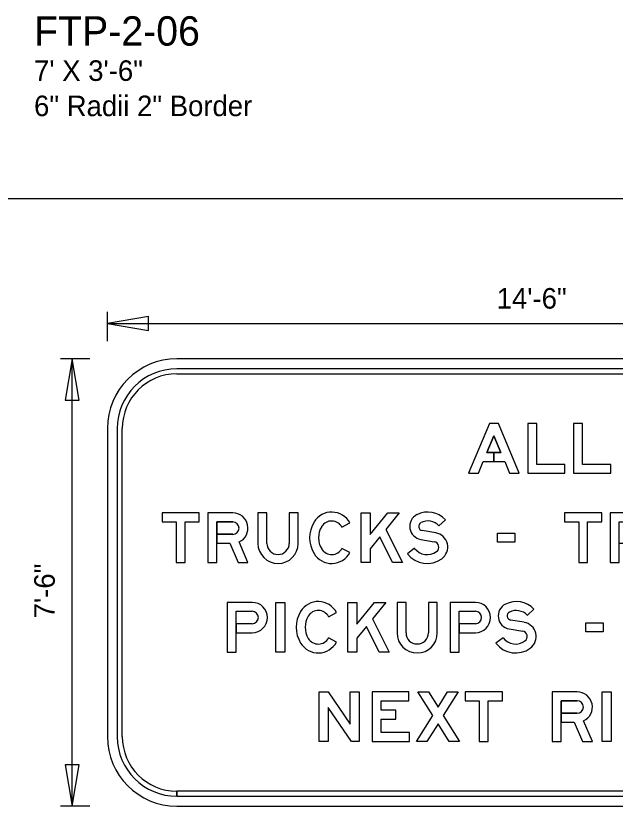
# Model space of a CAD drawing. Extents: x 0 to 770, y 0 to 495.
# Drawn here: x 195.9 to 297.9, y 226.6 to 361.1 of the extents above; entities that cross this region are included whole.
import ezdxf

# ---------------------------------------------------------------- set-up
doc = ezdxf.new("R2010")
doc.units = 0
for name, color, linetype in [('Dimension', 7, 'Continuous'), ('GSBWFill', 7, 'Continuous'), ('GSColorFill', 7, 'Continuous'), ('GSDims', 7, 'Continuous'), ('GSOutline', 7, 'Continuous'), ('SheetLines_dp', 7, 'Continuous'), ('TextStructures', 7, 'Continuous')]:
    doc.layers.add(name, color=color, linetype=linetype)

msp = doc.modelspace()

# ---------------------------------------------------------------- linework, layer by layer
at = {"layer": 'Dimension'}
for points in [[(211.47, 308.76), (218.49, 307.57), (218.49, 309.95)], [(205.48, 302.76), (204.29, 295.75), (206.67, 295.75)], [(205.48, 226.64), (206.67, 233.66), (204.29, 233.66)]]:
    msp.add_lwpolyline(points, close=True, dxfattribs=at)
at = {"layer": 'GSBWFill'}
for p, q in [((346.81, 302.76), (223.31, 302.76)), ((346.81, 301.07), (223.31, 301.07)), ((223.31, 300.23), (346.81, 300.23)), ((211.47, 290.92), (211.47, 238.48)), ((213.16, 290.92), (213.16, 238.48)), ((214.01, 238.48), (214.01, 290.92)), ((242.43, 276.54), (242.43, 271.36)), ((251.41, 274.12), (252.75, 274.83)), ((267.92, 274.34), (269.03, 275.38)), ((267.37, 273.15), (265.06, 273.54)), ((264.81, 272.04), (267.11, 271.65)), ((252.75, 269.8), (251.41, 270.51)), ((251.41, 270.51), (251.41, 270.51)), ((263.77, 270.52), (262.56, 269.59)), ((266.11, 261.32), (266.11, 256.14)), ((233.38, 259.8), (236.13, 259.8)), ((249.12, 258.89), (250.47, 259.61)), ((271.36, 259.8), (274.11, 259.8)), ((282.97, 259.12), (284.09, 260.16)), ((282.42, 257.93), (280.12, 258.31)), ((279.87, 256.81), (282.17, 256.42)), ((250.47, 254.57), (249.12, 255.29)), ((249.12, 255.29), (249.12, 255.29)), ((278.82, 255.29), (277.62, 254.36)), ((223.31, 228.33), (223.31, 229.18)), ((346.81, 229.18), (223.32, 229.18)), ((223.32, 229.18), (223.32, 228.33)), ((223.32, 228.33), (346.81, 228.33)), ((223.31, 226.64), (346.81, 226.64))]:
    msp.add_line(p, q, dxfattribs=at)
for points in [[(278.47, 286.82), (277.28, 286.82), (277.28, 285.3), (279.11, 285.3), (279.94, 283.31), (281.59, 283.31), (278.04, 291.77), (276.52, 291.77), (272.96, 283.31), (274.62, 283.31), (275.45, 285.3), (277.28, 285.3), (277.28, 286.82), (276.09, 286.82), (277.28, 289.65)], [(289.37, 283.31), (289.37, 284.79), (284.55, 284.79), (284.55, 291.77), (283.03, 291.77), (283.03, 283.31)], [(297.16, 283.31), (297.16, 284.79), (292.33, 284.79), (292.33, 291.77), (290.81, 291.77), (290.81, 283.31)], [(220.78, 275.02), (223.19, 275.02), (223.19, 268.09), (224.71, 268.09), (224.71, 275.02), (227.12, 275.02), (227.12, 276.54), (220.78, 276.54)], [(261.17, 276.54), (258.9, 273.75), (261.71, 268.09), (260.01, 268.09), (257.84, 272.45), (256.22, 270.45), (256.22, 268.09), (254.69, 268.09), (254.69, 276.54), (256.22, 276.54), (256.22, 272.87), (259.2, 276.54)], [(289.29, 275.02), (291.7, 275.02), (291.7, 268.09), (293.22, 268.09), (293.22, 275.02), (295.63, 275.02), (295.63, 276.54), (289.29, 276.54)], [(277.87, 273.08), (280.83, 273.08), (280.83, 271.55), (277.87, 271.55)], [(240.15, 252.86), (240.15, 261.32), (241.67, 261.32), (241.67, 252.86)], [(258.88, 261.32), (256.61, 258.53), (259.43, 252.86), (257.73, 252.86), (255.56, 257.23), (253.93, 255.23), (253.93, 252.86), (252.41, 252.86), (252.41, 261.32), (253.93, 261.32), (253.93, 257.64), (256.92, 261.32)], [(292.93, 257.85), (295.89, 257.85), (295.89, 256.33), (292.93, 256.33)], [(254.36, 246.09), (254.36, 237.64), (253.05, 237.64), (249.03, 243.43), (249.03, 237.64), (247.5, 237.64), (247.5, 246.09), (249.03, 246.09), (252.83, 240.61), (252.83, 246.09)], [(262.9, 239.16), (258.08, 239.16), (258.08, 241.43), (260.57, 241.43), (260.57, 242.96), (258.08, 242.96), (258.08, 244.57), (262.77, 244.57), (262.77, 246.09), (256.56, 246.09), (256.56, 237.64), (262.9, 237.64)], [(269.64, 237.64), (267.76, 240.63), (265.88, 237.64), (264.08, 237.64), (266.86, 242.07), (264.34, 246.09), (266.13, 246.09), (267.76, 243.5), (269.39, 246.09), (271.19, 246.09), (268.66, 242.07), (271.44, 237.64)], [(272.37, 244.57), (274.78, 244.57), (274.78, 237.64), (276.31, 237.64), (276.31, 244.57), (278.72, 244.57), (278.72, 246.09), (272.37, 246.09)], [(295.72, 237.64), (295.72, 246.09), (297.24, 246.09), (297.24, 237.64)]]:
    msp.add_lwpolyline(points, close=True, dxfattribs=at)
for points in [[(232.83, 276.54), (228.56, 276.54), (228.56, 268.09), (230.08, 268.09), (230.08, 275.02), (232.83, 275.02)], [(238.62, 271.36), (238.62, 276.54), (237.1, 276.54), (237.1, 271.36)], [(243.95, 271.36), (243.95, 276.54), (242.43, 276.54)], [(301.34, 276.54), (297.07, 276.54), (297.07, 268.09), (298.59, 268.09), (298.59, 275.02), (301.34, 275.02)], [(232.83, 272.91), (230.08, 272.91), (230.08, 271.38)], [(230.08, 271.38), (232.32, 271.38), (233.75, 268.09), (235.41, 268.09), (233.88, 271.61)], [(236.13, 261.32), (231.86, 261.32), (231.86, 252.86), (233.38, 252.86), (233.38, 259.8)], [(262.31, 256.14), (262.31, 261.32), (260.78, 261.32), (260.78, 256.14)], [(267.64, 256.14), (267.64, 261.32), (266.11, 261.32)], [(274.11, 261.32), (269.83, 261.32), (269.83, 252.86), (271.36, 252.86), (271.36, 259.8)], [(236.13, 257.68), (233.38, 257.68), (233.38, 256.16), (236.13, 256.16)], [(274.11, 257.68), (271.36, 257.68), (271.36, 256.16), (274.11, 256.16)], [(291.45, 246.09), (287.17, 246.09), (287.17, 237.64), (288.7, 237.64), (288.7, 244.57), (291.45, 244.57)], [(291.45, 242.46), (288.7, 242.46), (288.7, 240.93)], [(288.7, 240.93), (290.94, 240.93), (292.37, 237.64), (294.03, 237.64), (292.5, 241.16)]]:
    msp.add_lwpolyline(points, dxfattribs=at)
for centre, radius, start, end in [((223.31, 290.92), 11.84, 90, 180), ((223.31, 290.92), 10.15, 90, 180), ((223.31, 290.92), 9.3, 90, 180), ((265.18, 274.25), 2.24, 116.9123, 260.4087), ((266.03, 272.59), 4.1, 42.8759, 116.9123), ((265.18, 274.25), 0.719, 116.9123, 260.4087), ((266.03, 272.59), 2.58, 42.8759, 116.9123), ((266.96, 270.73), 2.45, 306.123, 80.4087), ((240.53, 271.36), 3.43, 180, 0), ((240.53, 271.36), 1.9, 180, 0), ((265.91, 272.17), 2.71, 217.5895, 306.123), ((266.96, 270.73), 0.93, 306.123, 80.4087), ((265.91, 272.17), 4.23, 217.5895, 306.123), ((236.13, 258.74), 2.58, 270, 90), ((280.24, 259.02), 2.24, 116.9123, 260.4087), ((281.08, 257.36), 4.1, 42.8759, 116.9123), ((236.13, 258.74), 1.06, 270, 90), ((280.24, 259.02), 0.719, 116.9123, 260.4087), ((281.08, 257.36), 2.58, 42.8759, 116.9123), ((282.01, 255.51), 2.45, 306.123, 80.4087), ((264.21, 256.14), 3.43, 180, 0), ((264.21, 256.14), 1.9, 180, 0), ((282.01, 255.51), 0.93, 306.123, 80.4087), ((280.97, 256.94), 4.23, 217.5895, 306.123), ((280.97, 256.94), 2.71, 217.5895, 306.123), ((223.31, 238.48), 11.84, 180, 270), ((223.31, 238.48), 10.15, 180, 270), ((223.31, 238.48), 9.3, 180, 270)]:
    msp.add_arc(centre, radius, start, end, dxfattribs=at)
for centre, major_axis, start_param, end_param in [((232.83, 273.96), (0, 2.58), 3.562504, 6.283185), ((249.65, 273.18), (0, 3.51), 5.201543, 7.308565), ((232.83, 273.96), (0, 1.06), 3.141593, 6.283185), ((251.08, 272.31), (0, 5.18), 1.025379, 2.116213), ((249.65, 273.18), (0, 1.99), 5.201543, 7.308565), ((251.08, 272.31), (0, 3.66), 1.025379, 2.116213), ((249.65, 271.45), (0, 1.99), 2.116213, 4.223235), ((249.65, 271.45), (0, 3.51), 2.116213, 4.223235), ((247.37, 257.96), (0, 3.51), 5.201543, 7.308565), ((274.11, 258.74), (0, 2.58), 3.141593, 6.283185), ((248.8, 257.09), (0, 5.18), 1.025379, 2.116213), ((247.37, 257.96), (0, 1.99), 5.201543, 7.308565), ((274.11, 258.74), (0, 1.06), 3.141593, 6.283185), ((248.8, 257.09), (0, 3.66), 1.025379, 2.116213), ((247.37, 256.22), (0, 3.51), 2.116213, 4.223235), ((247.37, 256.22), (0, 1.99), 2.116213, 4.223235), ((291.45, 243.51), (0, 2.58), 3.562504, 6.283185), ((291.45, 243.51), (0, 1.06), 3.141593, 6.283185)]:
    msp.add_ellipse(centre, major_axis=major_axis, ratio=0.999994, start_param=start_param, end_param=end_param, dxfattribs=at)
at = {"layer": 'GSColorFill'}
for p, q in [((242.43, 276.54), (242.43, 271.36)), ((251.41, 274.12), (252.75, 274.83)), ((267.92, 274.34), (269.03, 275.38)), ((267.37, 273.15), (265.06, 273.54)), ((264.81, 272.04), (267.11, 271.65)), ((252.75, 269.8), (251.41, 270.51)), ((251.41, 270.51), (251.41, 270.51)), ((263.77, 270.52), (262.56, 269.59)), ((266.11, 261.32), (266.11, 256.14)), ((233.38, 259.8), (236.13, 259.8)), ((249.12, 258.89), (250.47, 259.61)), ((271.36, 259.8), (274.11, 259.8)), ((282.97, 259.12), (284.09, 260.16)), ((282.42, 257.93), (280.12, 258.31)), ((279.87, 256.81), (282.17, 256.42)), ((250.47, 254.57), (249.12, 255.29)), ((249.12, 255.29), (249.12, 255.29)), ((278.82, 255.29), (277.62, 254.36))]:
    msp.add_line(p, q, dxfattribs=at)
for points in [[(278.47, 286.82), (277.28, 286.82), (277.28, 285.3), (279.11, 285.3), (279.94, 283.31), (281.59, 283.31), (278.04, 291.77), (276.52, 291.77), (272.96, 283.31), (274.62, 283.31), (275.45, 285.3), (277.28, 285.3), (277.28, 286.82), (276.09, 286.82), (277.28, 289.65)], [(289.37, 283.31), (289.37, 284.79), (284.55, 284.79), (284.55, 291.77), (283.03, 291.77), (283.03, 283.31)], [(297.16, 283.31), (297.16, 284.79), (292.33, 284.79), (292.33, 291.77), (290.81, 291.77), (290.81, 283.31)], [(220.78, 275.02), (223.19, 275.02), (223.19, 268.09), (224.71, 268.09), (224.71, 275.02), (227.12, 275.02), (227.12, 276.54), (220.78, 276.54)], [(261.17, 276.54), (258.9, 273.75), (261.71, 268.09), (260.01, 268.09), (257.84, 272.45), (256.22, 270.45), (256.22, 268.09), (254.69, 268.09), (254.69, 276.54), (256.22, 276.54), (256.22, 272.87), (259.2, 276.54)], [(289.29, 275.02), (291.7, 275.02), (291.7, 268.09), (293.22, 268.09), (293.22, 275.02), (295.63, 275.02), (295.63, 276.54), (289.29, 276.54)], [(277.87, 273.08), (280.83, 273.08), (280.83, 271.55), (277.87, 271.55)], [(240.15, 252.86), (240.15, 261.32), (241.67, 261.32), (241.67, 252.86)], [(258.88, 261.32), (256.61, 258.53), (259.43, 252.86), (257.73, 252.86), (255.56, 257.23), (253.93, 255.23), (253.93, 252.86), (252.41, 252.86), (252.41, 261.32), (253.93, 261.32), (253.93, 257.64), (256.92, 261.32)], [(292.93, 257.85), (295.89, 257.85), (295.89, 256.33), (292.93, 256.33)], [(254.36, 246.09), (254.36, 237.64), (253.05, 237.64), (249.03, 243.43), (249.03, 237.64), (247.5, 237.64), (247.5, 246.09), (249.03, 246.09), (252.83, 240.61), (252.83, 246.09)], [(262.9, 239.16), (258.08, 239.16), (258.08, 241.43), (260.57, 241.43), (260.57, 242.96), (258.08, 242.96), (258.08, 244.57), (262.77, 244.57), (262.77, 246.09), (256.56, 246.09), (256.56, 237.64), (262.9, 237.64)], [(269.64, 237.64), (267.76, 240.63), (265.88, 237.64), (264.08, 237.64), (266.86, 242.07), (264.34, 246.09), (266.13, 246.09), (267.76, 243.5), (269.39, 246.09), (271.19, 246.09), (268.66, 242.07), (271.44, 237.64)], [(272.37, 244.57), (274.78, 244.57), (274.78, 237.64), (276.31, 237.64), (276.31, 244.57), (278.72, 244.57), (278.72, 246.09), (272.37, 246.09)], [(295.72, 237.64), (295.72, 246.09), (297.24, 246.09), (297.24, 237.64)]]:
    msp.add_lwpolyline(points, close=True, dxfattribs=at)
for points in [[(232.83, 276.54), (228.56, 276.54), (228.56, 268.09), (230.08, 268.09), (230.08, 275.02), (232.83, 275.02)], [(238.62, 271.36), (238.62, 276.54), (237.1, 276.54), (237.1, 271.36)], [(243.95, 271.36), (243.95, 276.54), (242.43, 276.54)], [(301.34, 276.54), (297.07, 276.54), (297.07, 268.09), (298.59, 268.09), (298.59, 275.02), (301.34, 275.02)], [(232.83, 272.91), (230.08, 272.91), (230.08, 271.38)], [(230.08, 271.38), (232.32, 271.38), (233.75, 268.09), (235.41, 268.09), (233.88, 271.61)], [(236.13, 261.32), (231.86, 261.32), (231.86, 252.86), (233.38, 252.86), (233.38, 259.8)], [(262.31, 256.14), (262.31, 261.32), (260.78, 261.32), (260.78, 256.14)], [(267.64, 256.14), (267.64, 261.32), (266.11, 261.32)], [(274.11, 261.32), (269.83, 261.32), (269.83, 252.86), (271.36, 252.86), (271.36, 259.8)], [(236.13, 257.68), (233.38, 257.68), (233.38, 256.16), (236.13, 256.16)], [(274.11, 257.68), (271.36, 257.68), (271.36, 256.16), (274.11, 256.16)], [(291.45, 246.09), (287.17, 246.09), (287.17, 237.64), (288.7, 237.64), (288.7, 244.57), (291.45, 244.57)], [(291.45, 242.46), (288.7, 242.46), (288.7, 240.93)], [(288.7, 240.93), (290.94, 240.93), (292.37, 237.64), (294.03, 237.64), (292.5, 241.16)]]:
    msp.add_lwpolyline(points, dxfattribs=at)
for centre, radius, start, end in [((265.18, 274.25), 2.24, 116.9123, 260.4087), ((266.03, 272.59), 4.1, 42.8759, 116.9123), ((265.18, 274.25), 0.719, 116.9123, 260.4087), ((266.03, 272.59), 2.58, 42.8759, 116.9123), ((266.96, 270.73), 2.45, 306.123, 80.4087), ((240.53, 271.36), 3.43, 180, 0), ((240.53, 271.36), 1.9, 180, 0), ((265.91, 272.17), 2.71, 217.5895, 306.123), ((266.96, 270.73), 0.93, 306.123, 80.4087), ((265.91, 272.17), 4.23, 217.5895, 306.123), ((236.13, 258.74), 2.58, 270, 90), ((280.24, 259.02), 2.24, 116.9123, 260.4087), ((281.08, 257.36), 4.1, 42.8759, 116.9123), ((236.13, 258.74), 1.06, 270, 90), ((280.24, 259.02), 0.719, 116.9123, 260.4087), ((281.08, 257.36), 2.58, 42.8759, 116.9123), ((282.01, 255.51), 2.45, 306.123, 80.4087), ((264.21, 256.14), 3.43, 180, 0), ((264.21, 256.14), 1.9, 180, 0), ((282.01, 255.51), 0.93, 306.123, 80.4087), ((280.97, 256.94), 4.23, 217.5895, 306.123), ((280.97, 256.94), 2.71, 217.5895, 306.123)]:
    msp.add_arc(centre, radius, start, end, dxfattribs=at)
for centre, major_axis, start_param, end_param in [((232.83, 273.96), (0, 2.58), 3.562504, 6.283185), ((249.65, 273.18), (0, 3.51), 5.201543, 7.308565), ((232.83, 273.96), (0, 1.06), 3.141593, 6.283185), ((251.08, 272.31), (0, 5.18), 1.025379, 2.116213), ((249.65, 273.18), (0, 1.99), 5.201543, 7.308565), ((251.08, 272.31), (0, 3.66), 1.025379, 2.116213), ((249.65, 271.45), (0, 1.99), 2.116213, 4.223235), ((249.65, 271.45), (0, 3.51), 2.116213, 4.223235), ((247.37, 257.96), (0, 3.51), 5.201543, 7.308565), ((274.11, 258.74), (0, 2.58), 3.141593, 6.283185), ((248.8, 257.09), (0, 5.18), 1.025379, 2.116213), ((247.37, 257.96), (0, 1.99), 5.201543, 7.308565), ((274.11, 258.74), (0, 1.06), 3.141593, 6.283185), ((248.8, 257.09), (0, 3.66), 1.025379, 2.116213), ((247.37, 256.22), (0, 3.51), 2.116213, 4.223235), ((247.37, 256.22), (0, 1.99), 2.116213, 4.223235), ((291.45, 243.51), (0, 2.58), 3.562504, 6.283185), ((291.45, 243.51), (0, 1.06), 3.141593, 6.283185)]:
    msp.add_ellipse(centre, major_axis=major_axis, ratio=0.999994, start_param=start_param, end_param=end_param, dxfattribs=at)
at = {"layer": 'GSDims'}
for p, q in [((211.47, 305.76), (211.47, 310.76)), ((211.47, 308.76), (358.65, 308.76)), ((208.48, 302.76), (203.48, 302.76)), ((205.48, 226.64), (205.48, 302.76)), ((208.48, 226.64), (203.48, 226.64))]:
    msp.add_line(p, q, dxfattribs=at)
at = {"layer": 'GSOutline'}
for p, q in [((242.43, 276.54), (242.43, 271.36)), ((251.41, 274.12), (252.75, 274.83)), ((267.92, 274.34), (269.03, 275.38)), ((267.37, 273.15), (265.06, 273.54)), ((230.08, 272.91), (232.83, 272.91)), ((264.81, 272.04), (267.11, 271.65)), ((252.75, 269.8), (251.41, 270.51)), ((251.41, 270.51), (251.41, 270.51)), ((263.77, 270.52), (262.56, 269.59)), ((266.11, 261.32), (266.11, 256.14)), ((233.38, 259.8), (236.13, 259.8)), ((249.12, 258.89), (250.47, 259.61)), ((271.36, 259.8), (274.11, 259.8)), ((282.97, 259.12), (284.09, 260.16)), ((282.42, 257.93), (280.12, 258.31)), ((233.38, 256.16), (236.13, 256.16)), ((271.36, 256.16), (274.11, 256.16)), ((279.87, 256.81), (282.17, 256.42)), ((250.47, 254.57), (249.12, 255.29)), ((249.12, 255.29), (249.12, 255.29)), ((278.82, 255.29), (277.62, 254.36)), ((288.7, 242.46), (291.45, 242.46))]:
    msp.add_line(p, q, dxfattribs=at)
for points in [[(275.45, 285.3), (279.11, 285.3), (279.94, 283.31), (281.59, 283.31), (278.04, 291.77), (276.52, 291.77), (272.96, 283.31), (274.62, 283.31)], [(289.37, 283.31), (289.37, 284.79), (284.55, 284.79), (284.55, 291.77), (283.03, 291.77), (283.03, 283.31)], [(297.16, 283.31), (297.16, 284.79), (292.33, 284.79), (292.33, 291.77), (290.81, 291.77), (290.81, 283.31)], [(278.47, 286.82), (277.28, 289.65), (276.09, 286.82)], [(220.78, 275.02), (223.19, 275.02), (223.19, 268.09), (224.71, 268.09), (224.71, 275.02), (227.12, 275.02), (227.12, 276.54), (220.78, 276.54)], [(261.17, 276.54), (258.9, 273.75), (261.71, 268.09), (260.01, 268.09), (257.84, 272.45), (256.22, 270.45), (256.22, 268.09), (254.69, 268.09), (254.69, 276.54), (256.22, 276.54), (256.22, 272.87), (259.2, 276.54)], [(289.29, 275.02), (291.7, 275.02), (291.7, 268.09), (293.22, 268.09), (293.22, 275.02), (295.63, 275.02), (295.63, 276.54), (289.29, 276.54)], [(277.87, 273.08), (280.83, 273.08), (280.83, 271.55), (277.87, 271.55)], [(240.15, 252.86), (240.15, 261.32), (241.67, 261.32), (241.67, 252.86)], [(258.88, 261.32), (256.61, 258.53), (259.43, 252.86), (257.73, 252.86), (255.56, 257.23), (253.93, 255.23), (253.93, 252.86), (252.41, 252.86), (252.41, 261.32), (253.93, 261.32), (253.93, 257.64), (256.92, 261.32)], [(292.93, 257.85), (295.89, 257.85), (295.89, 256.33), (292.93, 256.33)], [(254.36, 246.09), (254.36, 237.64), (253.05, 237.64), (249.03, 243.43), (249.03, 237.64), (247.5, 237.64), (247.5, 246.09), (249.03, 246.09), (252.83, 240.61), (252.83, 246.09)], [(262.9, 239.16), (258.08, 239.16), (258.08, 241.43), (260.57, 241.43), (260.57, 242.96), (258.08, 242.96), (258.08, 244.57), (262.77, 244.57), (262.77, 246.09), (256.56, 246.09), (256.56, 237.64), (262.9, 237.64)], [(269.64, 237.64), (267.76, 240.63), (265.88, 237.64), (264.08, 237.64), (266.86, 242.07), (264.34, 246.09), (266.13, 246.09), (267.76, 243.5), (269.39, 246.09), (271.19, 246.09), (268.66, 242.07), (271.44, 237.64)], [(272.37, 244.57), (274.78, 244.57), (274.78, 237.64), (276.31, 237.64), (276.31, 244.57), (278.72, 244.57), (278.72, 246.09), (272.37, 246.09)], [(295.72, 237.64), (295.72, 246.09), (297.24, 246.09), (297.24, 237.64)]]:
    msp.add_lwpolyline(points, close=True, dxfattribs=at)
for points in [[(232.83, 276.54), (228.56, 276.54), (228.56, 268.09), (230.08, 268.09), (230.08, 271.38), (232.32, 271.38)], [(238.62, 271.36), (238.62, 276.54), (237.1, 276.54), (237.1, 271.36)], [(243.95, 271.36), (243.95, 276.54), (242.43, 276.54)], [(301.34, 276.54), (297.07, 276.54), (297.07, 268.09), (298.59, 268.09), (298.59, 271.38), (300.83, 271.38)], [(232.83, 275.02), (230.08, 275.02), (230.08, 272.91)], [(232.32, 271.38), (233.75, 268.09), (235.41, 268.09), (233.88, 271.61)], [(236.13, 261.32), (231.86, 261.32), (231.86, 252.86), (233.38, 252.86), (233.38, 256.16)], [(262.31, 256.14), (262.31, 261.32), (260.78, 261.32), (260.78, 256.14)], [(267.64, 256.14), (267.64, 261.32), (266.11, 261.32)], [(274.11, 261.32), (269.83, 261.32), (269.83, 252.86), (271.36, 252.86), (271.36, 256.16)], [(236.13, 257.68), (233.38, 257.68), (233.38, 259.8)], [(274.11, 257.68), (271.36, 257.68), (271.36, 259.8)], [(291.45, 246.09), (287.17, 246.09), (287.17, 237.64), (288.7, 237.64), (288.7, 240.93), (290.94, 240.93)], [(291.45, 244.57), (288.7, 244.57), (288.7, 242.46)], [(290.94, 240.93), (292.37, 237.64), (294.03, 237.64), (292.5, 241.16)]]:
    msp.add_lwpolyline(points, dxfattribs=at)
for centre, radius, start, end in [((265.18, 274.25), 2.24, 116.9123, 260.4087), ((266.03, 272.59), 4.1, 42.8759, 116.9123), ((265.18, 274.25), 0.719, 116.9123, 260.4087), ((266.03, 272.59), 2.58, 42.8759, 116.9123), ((266.96, 270.73), 2.45, 306.123, 80.4087), ((240.53, 271.36), 3.43, 180, 0), ((240.53, 271.36), 1.9, 180, 0), ((265.91, 272.17), 2.71, 217.5895, 306.123), ((266.96, 270.73), 0.93, 306.123, 80.4087), ((265.91, 272.17), 4.23, 217.5895, 306.123), ((236.13, 258.74), 2.58, 270, 90), ((280.24, 259.02), 2.24, 116.9123, 260.4087), ((281.08, 257.36), 4.1, 42.8759, 116.9123), ((236.13, 258.74), 1.06, 270, 90), ((280.24, 259.02), 0.719, 116.9123, 260.4087), ((281.08, 257.36), 2.58, 42.8759, 116.9123), ((282.01, 255.51), 2.45, 306.123, 80.4087), ((264.21, 256.14), 3.43, 180, 0), ((264.21, 256.14), 1.9, 180, 0), ((282.01, 255.51), 0.93, 306.123, 80.4087), ((280.97, 256.94), 4.23, 217.5895, 306.123), ((280.97, 256.94), 2.71, 217.5895, 306.123)]:
    msp.add_arc(centre, radius, start, end, dxfattribs=at)
for centre, major_axis, start_param, end_param in [((232.83, 273.96), (0, 2.58), 3.562504, 6.283185), ((249.65, 273.18), (0, 3.51), 5.201543, 7.308565), ((232.83, 273.96), (0, 1.06), 3.141593, 6.283185), ((251.08, 272.31), (0, 5.18), 1.025379, 2.116213), ((249.65, 273.18), (0, 1.99), 5.201543, 7.308565), ((251.08, 272.31), (0, 3.66), 1.025379, 2.116213), ((249.65, 271.45), (0, 1.99), 2.116213, 4.223235), ((249.65, 271.45), (0, 3.51), 2.116213, 4.223235), ((247.37, 257.96), (0, 3.51), 5.201543, 7.308565), ((274.11, 258.74), (0, 2.58), 3.141593, 6.283185), ((248.8, 257.09), (0, 5.18), 1.025379, 2.116213), ((247.37, 257.96), (0, 1.99), 5.201543, 7.308565), ((274.11, 258.74), (0, 1.06), 3.141593, 6.283185), ((248.8, 257.09), (0, 3.66), 1.025379, 2.116213), ((247.37, 256.22), (0, 3.51), 2.116213, 4.223235), ((247.37, 256.22), (0, 1.99), 2.116213, 4.223235), ((291.45, 243.51), (0, 2.58), 3.562504, 6.283185), ((291.45, 243.51), (0, 1.06), 3.141593, 6.283185)]:
    msp.add_ellipse(centre, major_axis=major_axis, ratio=0.999994, start_param=start_param, end_param=end_param, dxfattribs=at)
at = {"layer": 'SheetLines_dp'}
msp.add_line((770, 330), (0, 330), dxfattribs=at)

# ---------------------------------------------------------------- texts
at = {"layer": 'TextStructures'}
for s, height, p in [('FTP-2-06', 5, (198.99, 356.06)), ('7\' X 3\'-6"', 3.5, (198.99, 350.06)), ('6" Radii 2" Border', 3.5, (198.99, 344.06)), ('14\'-6"', 3.5, (277.74, 311.31))]:
    msp.add_text(s, height=height, dxfattribs=at).set_placement(p)
msp.add_text('7\'-6"', height=3.5, rotation=90, dxfattribs=at).set_placement((202.52, 258.6))

doc.saveas('drawing.dxf')
